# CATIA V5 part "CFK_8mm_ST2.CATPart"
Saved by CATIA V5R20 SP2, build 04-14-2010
Part number: CFK8_ST_2
Bounding box of the stored display mesh (mm): x -4 to 4, y -4 to 4, z 0 to 164
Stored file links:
  C:\Documents and Settings\Administrator\My Documents\Hobi_dokumenti\CAD_CNC\Clap_CATIA\CFK_8mm_ST2.CATPart
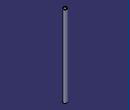
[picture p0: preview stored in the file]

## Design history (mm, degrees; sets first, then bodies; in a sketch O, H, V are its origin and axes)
Body1 (main body)
  Sketch1 on xy-plane, origin (0, 0, 0), H (1, 0, 0), V (0, 1, 0)
    circle A1 centre (0, 0) radius 3
    circle A2 centre (0, 0) radius 4
    radius A2 = 4
    radius A1 = 3
  Pad1: profile Sketch1, direction (0, 0, 1), length 164
  Chamfer1: length 0.2, angle 45, on edge [face of Pad1 from Sketch1.A2 | end face of Pad1]; edge [end face of Pad1 | face of Pad1 from Sketch1.A1]; start face of Pad1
